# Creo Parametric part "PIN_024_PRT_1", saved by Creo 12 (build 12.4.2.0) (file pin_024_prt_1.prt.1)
Units: Custom; MM, KILOGRAM, SECS

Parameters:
  PTC_WM_ITERATION = "0"
  PTC_WM_VERSION = "-.0"
  PTC_WM_LIFECYCLE_STATE = "In Work"
  PTC_WM_LIFECYCLE = "MO_CADDocument"
  PTC_WM_CREATED_BY = "Maximilian Roepper (Z0017RMS: MO)"
  PTC_WM_CREATED_ON = "18-Sep-26 11:36:42 AM"
  PTC_WM_MODIFIED_BY = "Maximilian Roepper (Z0017RMS: MO)"
  PTC_WM_MODIFIED_ON = "18-Sep-26 11:36:46 AM"
  PDMLINKNUMBER = "PDM000071454889"
  PTC_WM_NAME = "pin_024_prt_1.prt"
  PTC_WM_NUMBER = "PDM000071454889"

Other parameters: WEIGHT, WEIGHT_FACTOR, WEIGHT_ADD, _MASS_TEMP, _DIFF_TEMP, MC_ERRORS, SUPPLIER

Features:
  1. coordinate system
  2. datum plane "PRT_YZ"
  3. datum plane "PRT_XY"
  4. datum plane "PRT_XZ"
  5. coordinate system
  6. datum axis
  7. datum axis
  8. datum axis
  9. coordinate system
  10. imported feature
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
Other named items: PRT, SIEMENS_MO, DRW_VIEW_ORG, PRT_X, PRT_Y, PRT_Z, CS0, ROUGH_GROB

Layers: 00_STD_CSYS-KSYS, 01_STD_PLANES-EBENEN, 02_STD_AXES-ACHSEN, 03_STD_CSYS-KSYS, 24_IMPORT_FEAT-IMPORT_KE

Surfaces: 9 plane, 1 cylinder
